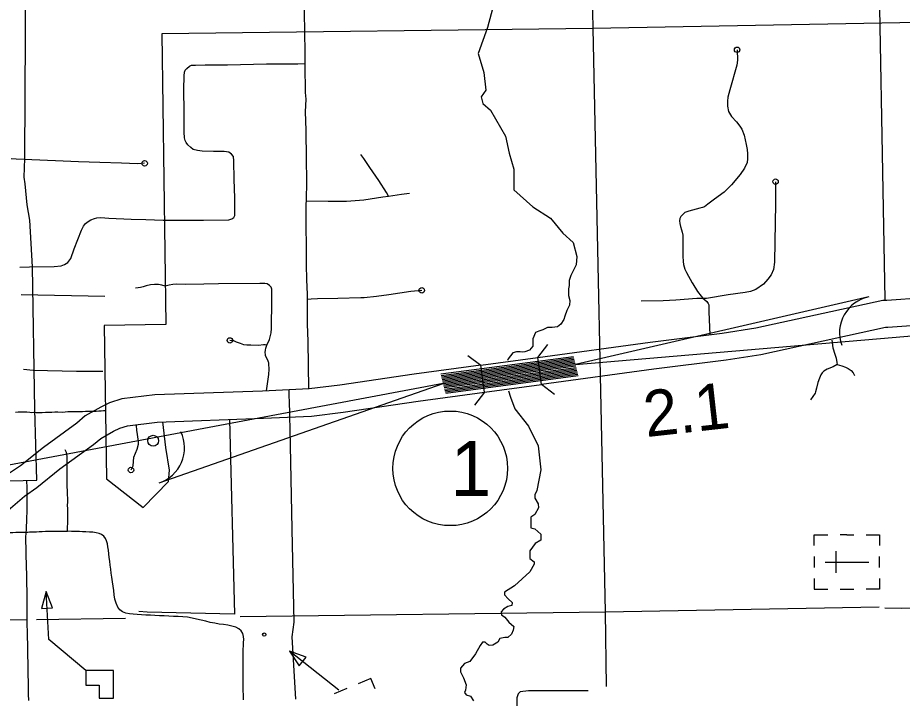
# Model space of a CAD drawing. Extents: x 1367863 to 1368197, y 380048 to 380261.
# Drawn here: x 1368012.13 to 1368043.62, y 380122.01 to 380146.25 of the extents above; entities that cross this region are included whole.
import ezdxf

# ---------------------------------------------------------------- set-up
doc = ezdxf.new("R2010")
doc.units = 0
for name, color, linetype in [('Level 10', 7, 'Continuous'), ('Level 31', 7, 'Continuous'), ('Level 32', 7, 'Continuous'), ('Level 33', 7, 'Continuous'), ('Level 35', 7, 'Continuous'), ('Level 37', 7, 'Continuous'), ('Level 48', 7, 'Continuous'), ('Level 5', 7, 'Continuous'), ('Level 57', 7, 'Continuous'), ('Level 58', 7, 'Continuous'), ('Level 6', 7, 'Continuous'), ('R_Border', 7, 'Continuous'), ('R_Dimension', 7, 'Continuous'), ('R_Draft', 7, 'Continuous')]:
    doc.layers.add(name, color=color, linetype=linetype)

msp = doc.modelspace()

# ---------------------------------------------------------------- linework, layer by layer
at = {"layer": 'Level 10'}
for points in [[(1368012.815, 380129.782), (1368012.748, 380132.296), (1368012.662, 380137.381), (1368012.568, 380139.037), (1368012.466, 380139.587), (1368012.395, 380140.33), (1368012.365, 380140.567), (1368012.387, 380141.231), (1368012.409, 380145.659), (1368012.399, 380151.1)], [(1368030.649, 380134.148), (1368034.65, 380134.691), (1368037.21, 380135.011), (1368038.401, 380135.199), (1368042.921, 380136.192), (1368043.069, 380136.191), (1368044.388, 380136.284)], [(1368044.428, 380135.314), (1368043.101, 380135.22), (1368043.024, 380135.221), (1368038.58, 380134.245), (1368037.346, 380134.05), (1368034.776, 380133.729), (1368030.779, 380133.187)], [(1368028.749, 380132.911), (1368028.618, 380133.873), (1368026.247, 380133.551), (1368023.595, 380133.158), (1368022.514, 380133.031), (1368020.845, 380132.951), (1368017.019, 380132.819), (1368015.838, 380132.673), (1368015.4, 380132.536), (1368015.088, 380132.377)], [(1368028.618, 380133.873), (1368030.649, 380134.148)], [(1368030.779, 380133.187), (1368030.649, 380134.148)], [(1368028.749, 380132.911), (1368030.779, 380133.187)], [(1368015.543, 380131.52), (1368015.767, 380131.634), (1368016.044, 380131.72), (1368017.096, 380131.85), (1368020.885, 380131.982), (1368022.594, 380132.064), (1368023.723, 380132.196), (1368026.384, 380132.591), (1368028.749, 380132.911)], [(1368015.088, 380132.377), (1368014.533, 380132.069), (1368014.234, 380131.812), (1368013.047, 380130.949), (1368012.237, 380130.295), (1368011.777, 380129.977)], [(1368011.633, 380128.564), (1368012.373, 380129.209), (1368012.818, 380129.517), (1368013.638, 380130.179), (1368014.837, 380131.051), (1368015.091, 380131.269), (1368015.543, 380131.52)], [(1368011.845, 380129.756), (1368012.815, 380129.782)]]:
    msp.add_lwpolyline(points, dxfattribs=at)
at = {"layer": 'Level 31'}
for points in [[(1368022.342, 380145.771), (1368022.342, 380145.735), (1368022.347, 380145.497), (1368022.352, 380145.261), (1368022.356, 380145.027), (1368022.36, 380144.794), (1368022.357, 380144.554), (1368022.371, 380143.587), (1368022.385, 380143.342), (1368022.375, 380143.122), (1368022.371, 380142.899), (1368022.388, 380142.239), (1368022.391, 380142.029), (1368022.393, 380141.824), (1368022.396, 380141.627), (1368022.4, 380141.437), (1368022.403, 380141.256), (1368022.404, 380141.082), (1368022.407, 380140.914), (1368022.409, 380140.752), (1368022.413, 380140.596), (1368022.415, 380140.446), (1368022.408, 380140.153), (1368022.404, 380140.015), (1368022.4, 380139.881), (1368022.397, 380139.743), (1368022.394, 380139.609), (1368022.393, 380139.473), (1368022.393, 380139.325), (1368022.391, 380139.176), (1368022.39, 380139.024), (1368022.39, 380138.866), (1368022.39, 380138.709), (1368022.394, 380138.547), (1368022.398, 380138.383), (1368022.4, 380138.211), (1368022.4, 380138.047), (1368022.404, 380137.886), (1368022.401, 380137.724), (1368022.406, 380137.571), (1368022.407, 380137.419), (1368022.405, 380137.261), (1368022.408, 380137.118), (1368022.412, 380136.976), (1368022.417, 380136.853), (1368022.421, 380136.721), (1368022.427, 380136.59), (1368022.432, 380136.459), (1368022.438, 380136.19), (1368022.435, 380136.043), (1368022.435, 380135.892), (1368022.434, 380135.737), (1368022.435, 380135.581), (1368022.438, 380135.423), (1368022.442, 380135.266), (1368022.447, 380135.11), (1368022.453, 380134.953), (1368022.456, 380134.806), (1368022.457, 380134.655), (1368022.46, 380134.499), (1368022.464, 380134.363), (1368022.469, 380134.23), (1368022.473, 380134.096), (1368022.476, 380133.976), (1368022.476, 380133.852), (1368022.474, 380133.733), (1368022.476, 380133.619), (1368022.477, 380133.509), (1368022.482, 380133.405), (1368022.487, 380133.305), (1368022.489, 380133.205), (1368022.488, 380133.03)], [(1368037.741, 380145.105), (1368037.75, 380144.733), (1368037.725, 380144.553), (1368037.48, 380143.681), (1368037.414, 380143.419), (1368037.398, 380143.272), (1368037.402, 380143.096), (1368037.435, 380142.908), (1368037.537, 380142.728), (1368037.713, 380142.544), (1368037.836, 380142.392), (1368037.905, 380142.282), (1368037.987, 380142.065), (1368038.065, 380141.731), (1368038.098, 380141.559), (1368038.11, 380141.395), (1368038.114, 380141.219), (1368038.093, 380141.092), (1368037.999, 380140.888), (1368037.844, 380140.667), (1368037.541, 380140.301), (1368037.275, 380140.039), (1368036.936, 380139.785), (1368036.694, 380139.605), (1368036.58, 380139.515), (1368036.51, 380139.49), (1368036.416, 380139.47), (1368036.023, 380139.36), (1368035.884, 380139.306), (1368035.831, 380139.269), (1368035.737, 380139.166), (1368035.704, 380139.1), (1368035.692, 380139.01), (1368035.696, 380138.924), (1368035.721, 380138.818), (1368035.762, 380138.699), (1368035.79, 380138.609), (1368035.803, 380138.507), (1368035.803, 380138.302), (1368035.807, 380137.754), (1368035.819, 380137.562), (1368035.827, 380137.455), (1368035.88, 380137.288), (1368035.942, 380137.177), (1368036.138, 380136.813), (1368036.161, 380136.766)], [(1368017.354, 380139.042), (1368018.006, 380139.036), (1368018.749, 380139.042), (1368019.652, 380139.049), (1368019.759, 380139.087), (1368019.822, 380139.137), (1368019.866, 380139.207), (1368019.866, 380139.301), (1368019.86, 380139.838), (1368019.841, 380140.489), (1368019.829, 380141.148), (1368019.81, 380141.306), (1368019.74, 380141.394), (1368019.645, 380141.464), (1368019.481, 380141.483), (1368019.109, 380141.483), (1368018.698, 380141.496), (1368018.528, 380141.514), (1368018.383, 380141.559), (1368018.301, 380141.628), (1368018.193, 380141.717), (1368018.13, 380141.799), (1368018.092, 380141.881), (1368018.067, 380141.976), (1368018.061, 380142.171), (1368018.054, 380142.891), (1368018.048, 380143.694), (1368018.054, 380144.176), (1368018.073, 380144.315), (1368018.099, 380144.378), (1368018.155, 380144.441), (1368018.244, 380144.517), (1368018.326, 380144.555), (1368018.465, 380144.561), (1368018.806, 380144.574), (1368019.601, 380144.574), (1368020.99, 380144.606), (1368021.764, 380144.606), (1368022.099, 380144.606), (1368022.358, 380144.612)], [(1368025.331, 380139.895), (1368025.261, 380140.026), (1368024.987, 380140.448), (1368024.672, 380140.91), (1368024.455, 380141.233), (1368024.353, 380141.376)], [(1368039.11, 380140.408), (1368039.106, 380139.626), (1368039.081, 380138.267), (1368039.065, 380137.547), (1368039.036, 380137.284), (1368038.95, 380137.087), (1368038.839, 380136.938), (1368038.685, 380136.755), (1368038.406, 380136.572), (1368038.214, 380136.495), (1368038.021, 380136.461), (1368037.42, 380136.379), (1368036.655, 380136.254), (1368036.304, 380136.244), (1368035.564, 380136.186), (1368035.111, 380136.171), (1368034.329, 380136.16)], [(1368022.397, 380139.727), (1368023.184, 380139.717), (1368023.842, 380139.717), (1368024.45, 380139.767), (1368025.127, 380139.867), (1368025.331, 380139.895), (1368025.797, 380139.969), (1368026.079, 380140.002)], [(1368021.007, 380134.589), (1368021.101, 380134.787), (1368021.153, 380135.024), (1368021.172, 380135.175), (1368021.172, 380135.315), (1368021.178, 380136.061), (1368021.175, 380136.576), (1368021.156, 380136.653), (1368021.101, 380136.713), (1368021.01, 380136.766), (1368020.933, 380136.782), (1368020.749, 380136.782), (1368019.282, 380136.768), (1368018.759, 380136.757), (1368018.121, 380136.752), (1368017.789, 380136.755), (1368017.657, 380136.744), (1368017.523, 380136.724), (1368017.378, 380136.683)], [(1368036.161, 380136.766), (1368036.335, 380136.499), (1368036.455, 380136.327), (1368036.518, 380136.264), (1368036.658, 380136.139), (1368036.71, 380136.077), (1368036.731, 380136.019), (1368036.736, 380135.769), (1368036.775, 380134.957)], [(1368026.518, 380136.538), (1368026.129, 380136.495), (1368025.338, 380136.38), (1368024.899, 380136.322), (1368024.46, 380136.272), (1368024.349, 380136.273), (1368023.524, 380136.253), (1368022.808, 380136.234), (1368022.578, 380136.225), (1368022.437, 380136.218)], [(1368021.007, 380134.589), (1368020.947, 380134.6), (1368020.886, 380134.597), (1368020.71, 380134.581), (1368020.435, 380134.586), (1368020.287, 380134.586), (1368020.182, 380134.603), (1368020.061, 380134.641), (1368019.926, 380134.691), (1368019.827, 380134.738), (1368019.687, 380134.757)], [(1368020.993, 380132.958), (1368021.07, 380133.546), (1368021.079, 380133.738), (1368021.07, 380133.923), (1368021.07, 380133.959), (1368021.062, 380133.984), (1368021.035, 380134.055), (1368020.969, 380134.182), (1368020.952, 380134.223), (1368020.949, 380134.253), (1368020.947, 380134.322), (1368020.955, 380134.413), (1368020.966, 380134.476), (1368021.007, 380134.589)], [(1368041.107, 380134.763), (1368041.149, 380134.496), (1368041.214, 380134.268), (1368041.263, 380134.123), (1368041.293, 380133.974), (1368041.298, 380133.904), (1368041.157, 380133.816), (1368040.951, 380133.737), (1368040.828, 380133.667), (1368040.767, 380133.606), (1368040.719, 380133.535), (1368040.671, 380133.413), (1368040.618, 380133.255), (1368040.565, 380133.062), (1368040.535, 380132.926), (1368040.513, 380132.873), (1368040.438, 380132.763), (1368040.355, 380132.645)], [(1368041.298, 380133.904), (1368041.464, 380133.856), (1368041.6, 380133.803), (1368041.697, 380133.755), (1368041.802, 380133.68), (1368041.868, 380133.597), (1368041.92, 380133.509)], [(1368016.347, 380131.73), (1368016.361, 380131.565), (1368016.422, 380131.17), (1368016.425, 380131.05), (1368016.372, 380130.871), (1368016.254, 380130.591), (1368016.243, 380130.451), (1368016.236, 380130.283), (1368016.165, 380130.141)], [(1368010.811, 380127.873), (1368010.881, 380127.878), (1368010.954, 380127.883), (1368011.029, 380127.887), (1368011.104, 380127.892), (1368011.181, 380127.897), (1368011.262, 380127.901), (1368011.348, 380127.905), (1368011.44, 380127.909), (1368011.536, 380127.911), (1368011.637, 380127.914), (1368011.743, 380127.918), (1368011.85, 380127.919), (1368011.958, 380127.922), (1368012.065, 380127.924), (1368012.163, 380127.927), (1368012.241, 380127.93), (1368012.29, 380127.93), (1368012.378, 380127.931), (1368012.429, 380127.932), (1368012.441, 380127.932)], [(1368012.477, 380124.632), (1368012.477, 380124.815), (1368012.467, 380125.024), (1368012.472, 380125.236), (1368012.471, 380125.444), (1368012.47, 380125.652), (1368012.467, 380125.859), (1368012.462, 380126.063), (1368012.457, 380126.264), (1368012.457, 380126.461), (1368012.452, 380126.66), (1368012.444, 380126.849), (1368012.437, 380127.025), (1368012.434, 380127.182), (1368012.434, 380127.313), (1368012.43, 380127.428), (1368012.425, 380127.531), (1368012.428, 380127.616), (1368012.429, 380127.692), (1368012.429, 380127.763), (1368012.437, 380127.883), (1368012.441, 380127.932)], [(1368012.441, 380127.932), (1368012.446, 380127.998), (1368012.451, 380128.09)], [(1368012.441, 380127.932), (1368012.491, 380127.933), (1368012.56, 380127.936), (1368012.636, 380127.939), (1368012.718, 380127.942), (1368012.807, 380127.945), (1368012.904, 380127.949), (1368013.008, 380127.954), (1368013.118, 380127.958), (1368013.232, 380127.96), (1368013.347, 380127.962), (1368013.46, 380127.964), (1368013.568, 380127.964), (1368013.666, 380127.962), (1368013.748, 380127.962), (1368013.911, 380127.966)], [(1368013.911, 380127.966), (1368013.912, 380128.094)], [(1368020.17, 380121.96), (1368020.167, 380122.123), (1368020.164, 380122.285), (1368020.161, 380122.445), (1368020.16, 380122.602), (1368020.16, 380122.757), (1368020.159, 380122.911), (1368020.159, 380123.063), (1368020.159, 380123.209), (1368020.154, 380123.36), (1368020.157, 380123.497), (1368020.16, 380123.63), (1368020.162, 380123.757), (1368020.166, 380123.878), (1368020.172, 380123.994), (1368020.179, 380124.106), (1368020.174, 380124.213), (1368020.146, 380124.317), (1368020.088, 380124.409), (1368020.004, 380124.486), (1368019.893, 380124.545), (1368019.759, 380124.584), (1368019.614, 380124.614), (1368019.464, 380124.635), (1368019.308, 380124.656), (1368019.149, 380124.685), (1368018.986, 380124.714), (1368018.825, 380124.755), (1368018.665, 380124.797), (1368018.504, 380124.835), (1368018.343, 380124.871), (1368018.181, 380124.896), (1368018.014, 380124.912), (1368017.848, 380124.92), (1368017.679, 380124.929), (1368017.511, 380124.938), (1368017.343, 380124.946), (1368017.18, 380124.952), (1368017.018, 380124.96), (1368016.857, 380124.97), (1368016.698, 380124.978), (1368016.541, 380124.986), (1368016.388, 380124.995), (1368016.241, 380125.007), (1368016.108, 380125.017), (1368015.982, 380125.044), (1368015.87, 380125.096), (1368015.773, 380125.168), (1368015.695, 380125.263), (1368015.637, 380125.395), (1368015.597, 380125.544), (1368015.572, 380125.699), (1368015.555, 380125.845), (1368015.532, 380126.007), (1368015.511, 380126.165), (1368015.486, 380126.32), (1368015.462, 380126.467), (1368015.445, 380126.614), (1368015.428, 380126.756), (1368015.413, 380126.895), (1368015.395, 380127.028), (1368015.379, 380127.161), (1368015.364, 380127.283), (1368015.348, 380127.4), (1368015.327, 380127.51), (1368015.298, 380127.616), (1368015.258, 380127.708), (1368015.199, 380127.783), (1368015.122, 380127.841), (1368015.031, 380127.881), (1368014.927, 380127.907), (1368014.811, 380127.923), (1368014.686, 380127.933), (1368014.565, 380127.94), (1368014.445, 380127.945), (1368014.333, 380127.95), (1368014.228, 380127.949), (1368014.134, 380127.953), (1368014.05, 380127.956), (1368013.911, 380127.966)], [(1368047.184, 380125.273), (1368046.31, 380125.259), (1368045.594, 380125.259), (1368045.157, 380125.266), (1368044.488, 380125.233), (1368043.594, 380125.213), (1368042.998, 380125.22)], [(1368012.525, 380121.929), (1368012.521, 380122.162), (1368012.517, 380122.389), (1368012.513, 380122.614), (1368012.51, 380122.837), (1368012.506, 380123.059), (1368012.504, 380123.282), (1368012.499, 380123.507), (1368012.493, 380123.731), (1368012.489, 380123.956), (1368012.488, 380124.177), (1368012.479, 380124.393), (1368012.477, 380124.632)]]:
    msp.add_lwpolyline(points, dxfattribs=at)
for centre in [(1368037.741, 380145.105), (1368039.11, 380140.408), (1368026.518, 380136.538), (1368019.687, 380134.757), (1368016.165, 380130.141)]:
    msp.add_circle(centre, 0.097, dxfattribs=at)
at = {"layer": 'Level 32'}
for points in [[(1368043.011, 380136.212), (1368042.731, 380151.129), (1368042.659, 380154.556), (1368042.643, 380154.618), (1368042.607, 380154.662), (1368042.594, 380154.674), (1368042.578, 380154.694), (1368042.51, 380154.734), (1368041.154, 380154.752)], [(1368032.436, 380122.274), (1368030.311, 380122.274), (1368030.018, 380122.244), (1368029.951, 380122.177), (1368029.898, 380122.027), (1368029.906, 380121.381), (1368029.921, 380120.419), (1368029.951, 380119.69), (1368029.958, 380119.375)]]:
    msp.add_lwpolyline(points, dxfattribs=at)
at = {"layer": 'Level 33'}
for points in [[(1368022.251, 380150.262), (1368022.259, 380150.054), (1368022.268, 380149.846), (1368022.274, 380149.639), (1368022.278, 380149.432), (1368022.283, 380149.211), (1368022.283, 380149.004), (1368022.286, 380148.799), (1368022.287, 380148.593), (1368022.288, 380148.388), (1368022.291, 380148.184), (1368022.296, 380147.976), (1368022.302, 380147.766), (1368022.306, 380147.556), (1368022.31, 380147.334), (1368022.313, 380147.114), (1368022.316, 380146.892), (1368022.324, 380146.667), (1368022.328, 380146.439), (1368022.334, 380146.207), (1368022.339, 380145.972), (1368022.342, 380145.771)], [(1368016.652, 380141.063), (1368016.403, 380141.048), (1368015.83, 380141.068), (1368015.058, 380141.093), (1368014.301, 380141.113), (1368013.479, 380141.148), (1368012.642, 380141.188), (1368012.084, 380141.207), (1368011.907, 380141.218)], [(1368012.211, 380137.362), (1368012.558, 380137.381), (1368013.436, 380137.394), (1368013.682, 380137.407), (1368013.795, 380137.457), (1368013.915, 380137.527), (1368014.023, 380137.678), (1368014.149, 380138.013), (1368014.402, 380138.682), (1368014.477, 380138.828), (1368014.547, 380138.916), (1368014.641, 380138.992), (1368014.742, 380139.055), (1368014.862, 380139.099), (1368014.951, 380139.125), (1368015.09, 380139.137), (1368015.374, 380139.112), (1368016.169, 380139.074), (1368016.693, 380139.061), (1368017.312, 380139.042), (1368017.354, 380139.042)], [(1368017.378, 380136.683), (1368017.268, 380136.724), (1368017.141, 380136.746), (1368017.006, 380136.752), (1368016.855, 380136.741), (1368016.707, 380136.705), (1368016.605, 380136.664), (1368016.5, 380136.639), (1368016.423, 380136.625), (1368016.33, 380136.617)], [(1368012.258, 380136.395), (1368015.234, 380136.33)], [(1368015.161, 380133.647), (1368014.223, 380133.647), (1368012.686, 380133.688), (1368012.341, 380133.715)], [(1368012.379, 380132.198), (1368012.317, 380132.196), (1368012.239, 380132.196), (1368012.151, 380132.196), (1368012.051, 380132.192)], [(1368015.257, 380132.249), (1368015.193, 380132.247), (1368015.108, 380132.241), (1368015.021, 380132.236), (1368014.932, 380132.23), (1368014.841, 380132.23), (1368014.746, 380132.23), (1368014.646, 380132.225), (1368014.545, 380132.224), (1368014.445, 380132.219), (1368014.339, 380132.216), (1368014.235, 380132.213), (1368014.127, 380132.213), (1368013.917, 380132.209), (1368013.818, 380132.201), (1368013.723, 380132.191), (1368013.568, 380132.203), (1368013.457, 380132.2), (1368013.354, 380132.194), (1368013.233, 380132.192), (1368013.121, 380132.187), (1368013.007, 380132.183), (1368012.896, 380132.181), (1368012.794, 380132.182), (1368012.703, 380132.184), (1368012.623, 380132.183), (1368012.561, 380132.188), (1368012.465, 380132.196), (1368012.379, 380132.198)], [(1368013.912, 380128.094), (1368013.912, 380128.138), (1368013.917, 380128.209), (1368013.918, 380128.281), (1368013.92, 380128.364), (1368013.92, 380128.453), (1368013.918, 380128.551), (1368013.916, 380128.656), (1368013.914, 380128.766), (1368013.912, 380128.883), (1368013.915, 380129.008), (1368013.915, 380129.136), (1368013.909, 380129.263), (1368013.905, 380129.407), (1368013.899, 380129.542), (1368013.897, 380129.685), (1368013.895, 380129.831), (1368013.893, 380129.978), (1368013.891, 380130.121), (1368013.891, 380130.264), (1368013.891, 380130.397), (1368013.892, 380130.519), (1368013.894, 380130.625), (1368013.888, 380130.707), (1368013.875, 380130.76), (1368013.826, 380130.864)], [(1368012.451, 380128.09), (1368012.453, 380128.166), (1368012.456, 380128.267), (1368012.46, 380128.375), (1368012.464, 380128.489), (1368012.469, 380128.605), (1368012.473, 380128.723), (1368012.475, 380128.842), (1368012.475, 380128.959), (1368012.476, 380129.07), (1368012.474, 380129.174), (1368012.472, 380129.271), (1368012.47, 380129.361), (1368012.469, 380129.443), (1368012.468, 380129.516), (1368012.461, 380129.762)]]:
    msp.add_lwpolyline(points, dxfattribs=at)
msp.add_circle((1368016.652, 380141.063), 0.097, dxfattribs=at)
at = {"layer": 'Level 35'}
for points in [[(1368029.116, 380146.89), (1368028.859, 380145.904), (1368028.525, 380144.968), (1368028.726, 380144.299), (1368028.792, 380143.663), (1368028.625, 380143.429), (1368028.692, 380143.195), (1368028.96, 380142.961), (1368029.495, 380142.025), (1368029.629, 380141.423), (1368029.796, 380140.854), (1368029.796, 380140.486), (1368029.796, 380140.119), (1368030.465, 380139.517), (1368031.1, 380139.115), (1368031.535, 380138.58), (1368031.903, 380138.246), (1368032.037, 380137.744), (1368032.012, 380137.45), (1368031.818, 380137.07), (1368031.762, 380136.894), (1368031.762, 380136.718), (1368031.744, 380136.598), (1368031.744, 380136.468), (1368031.744, 380136.357)], [(1368031.744, 380136.357), (1368031.79, 380136.181), (1368031.771, 380136.014), (1368031.679, 380135.82), (1368031.605, 380135.616), (1368031.568, 380135.505), (1368031.466, 380135.338), (1368031.346, 380135.237), (1368031.161, 380135.218), (1368030.994, 380135.218), (1368030.827, 380135.135), (1368030.679, 380135.088), (1368030.559, 380135.033), (1368030.475, 380134.811), (1368030.475, 380134.699), (1368030.475, 380134.551), (1368030.355, 380134.412), (1368030.189, 380134.348), (1368030.114, 380134.338), (1368030.013, 380134.348), (1368029.883, 380134.348), (1368029.763, 380134.31), (1368029.596, 380134.097), (1368029.572, 380134.043)], [(1368029.606, 380132.963), (1368029.679, 380132.741), (1368029.828, 380132.325), (1368030.317, 380131.698), (1368030.655, 380131.002), (1368030.754, 380130.148), (1368030.615, 380129.412), (1368030.536, 380129.253), (1368030.536, 380129.134), (1368030.655, 380128.936), (1368030.675, 380128.796), (1368030.536, 380128.558), (1368030.397, 380128.459), (1368030.397, 380128.081), (1368030.536, 380128.041), (1368030.754, 380127.862), (1368030.754, 380127.644), (1368030.556, 380127.524), (1368030.357, 380127.266), (1368030.357, 380126.988), (1368030.516, 380126.869), (1368030.516, 380126.789), (1368030.357, 380126.511), (1368029.82, 380126.014), (1368029.466, 380125.794), (1368029.466, 380125.702), (1368029.587, 380125.553), (1368029.735, 380125.424), (1368029.726, 380125.313), (1368029.578, 380125.276), (1368029.42, 380125.192), (1368029.346, 380125.09), (1368029.355, 380124.989), (1368029.476, 380124.896), (1368029.615, 380124.72), (1368029.79, 380124.563), (1368029.772, 380124.442), (1368029.707, 380124.294), (1368029.578, 380124.183), (1368029.476, 380124.183), (1368029.3, 380124.137), (1368029.226, 380124.016), (1368029.041, 380123.905), (1368028.911, 380123.896), (1368028.846, 380123.942), (1368028.772, 380124.016), (1368028.68, 380124.016), (1368028.596, 380123.896), (1368028.43, 380123.59), (1368028.226, 380123.322), (1368028.032, 380123.248), (1368027.893, 380123.09), (1368027.893, 380122.951), (1368028.004, 380122.738), (1368028.096, 380122.497), (1368028.069, 380122.307), (1368028.041, 380122.214), (1368028.096, 380122.14), (1368028.254, 380122.085), (1368028.356, 380121.927)]]:
    msp.add_lwpolyline(points, dxfattribs=at)
at = {"layer": 'Level 37'}
for points in [[(1368030.649, 380134.148), (1368031.002, 380134.611)], [(1368028.155, 380134.225), (1368028.618, 380133.873)], [(1368031.243, 380132.834), (1368030.779, 380133.187)], [(1368028.749, 380132.911), (1368028.396, 380132.448)]]:
    msp.add_lwpolyline(points, dxfattribs=at)
at = {"layer": 'Level 5'}
for points in [[(1368052.541, 380146.238), (1368032.607, 380145.868)], [(1368032.607, 380145.868), (1368033.044, 380125.092)], [(1368020.052, 380124.92), (1368033.044, 380125.092)], [(1368033.044, 380125.092), (1368042.795, 380125.271)], [(1368033.044, 380125.092), (1368033.083, 380122.436)], [(1368008.395, 380124.769), (1368012.457, 380124.82)], [(1368012.803, 380124.82), (1368015.976, 380124.862)]]:
    msp.add_lwpolyline(points, dxfattribs=at)
at = {"layer": 'Level 57'}
for p, q in [((1368041.649, 380127.836), (1368041.41, 380127.836)), ((1368041.649, 380127.836), (1368041.895, 380127.836)), ((1368040.485, 380127.062), (1368040.485, 380126.674)), ((1368041.261, 380126.477), (1368041.261, 380127.257)), ((1368042.813, 380126.674), (1368042.813, 380127.062)), ((1368040.873, 380126.865), (1368042.425, 380126.865)), ((1368041.649, 380126.865), (1368041.649, 380126.865)), ((1368041.649, 380126.865), (1368041.649, 380126.865)), ((1368041.41, 380125.895), (1368041.895, 380125.895)), ((1368023.849, 380122.361), (1368023.4, 380122.176))]:
    msp.add_line(p, q, dxfattribs=at)
for points in [[(1368040.485, 380127.448), (1368040.485, 380127.836), (1368040.97, 380127.836)], [(1368042.328, 380127.836), (1368042.813, 380127.836), (1368042.813, 380127.448)], [(1368040.485, 380126.283), (1368040.485, 380125.895), (1368040.97, 380125.895)], [(1368042.813, 380126.283), (1368042.813, 380125.895), (1368042.328, 380125.895)], [(1368023.562, 380122.303), (1368021.809, 380123.696)], [(1368024.852, 380122.355), (1368024.704, 380122.714), (1368024.256, 380122.529)]]:
    msp.add_lwpolyline(points, dxfattribs=at)
msp.add_lwpolyline([(1368022.151, 380123.172), (1368022.397, 380123.482), (1368021.809, 380123.696)], close=True, dxfattribs=at)
msp.add_circle((1368020.91, 380124.281), 0.0582, dxfattribs=at)
at = {"layer": 'Level 58'}
for points in [[(1368012.982, 380125.214), (1368013.377, 380125.236), (1368013.146, 380125.818)], [(1368015.548, 380122.997), (1368014.562, 380122.997), (1368014.562, 380122.477), (1368015.029, 380122.477), (1368015.029, 380122.011), (1368015.548, 380122.011)]]:
    msp.add_lwpolyline(points, close=True, dxfattribs=at)
msp.add_lwpolyline([(1368014.562, 380122.997), (1368013.242, 380124.102), (1368013.146, 380125.818)], dxfattribs=at)
msp.add_circle((1368016.956, 380131.183), 0.194, dxfattribs=at)
at = {"layer": 'Level 6'}
for points in [[(1368032.386, 380156.557), (1368032.607, 380145.868)], [(1368032.607, 380145.868), (1368017.259, 380145.675)], [(1368017.259, 380145.675), (1368017.408, 380135.32), (1368015.213, 380135.286)], [(1368015.213, 380135.286), (1368015.292, 380129.824)], [(1368015.292, 380129.824), (1368016.595, 380128.811), (1368017.499, 380129.727), (1368017.533, 380130.134), (1368017.409, 380130.948), (1368017.294, 380131.857)], [(1368019.668, 380131.94), (1368019.852, 380125.011)], [(1368019.849, 380125.011), (1368016.742, 380125.082), (1368016.449, 380125.099)]]:
    msp.add_lwpolyline(points, dxfattribs=at)
at = {"layer": 'R_Border'}
msp.add_lwpolyline([(1368022.031, 380121.983), (1368021.909, 380124.203), (1368021.973, 380124.721), (1368021.905, 380128.04), (1368021.845, 380131.019), (1368021.807, 380132.633), (1368021.796, 380132.728), (1368021.794, 380132.888), (1368021.799, 380133.01)], dxfattribs=at)
msp.add_circle((1368027.528, 380130.201), 2.041, dxfattribs=at)
at = {"layer": 'R_Dimension'}
for p, q in [((1368027.194, 380133.562), (1368031.915, 380134.188)), ((1368027.206, 380133.513), (1368031.928, 380134.139)), ((1368027.218, 380133.464), (1368031.94, 380134.09)), ((1368027.231, 380133.415), (1368031.952, 380134.041)), ((1368027.243, 380133.367), (1368031.965, 380133.992)), ((1368027.255, 380133.318), (1368031.977, 380133.944)), ((1368027.268, 380133.269), (1368031.989, 380133.895)), ((1368027.28, 380133.22), (1368032.002, 380133.846)), ((1368027.292, 380133.171), (1368032.014, 380133.797)), ((1368027.305, 380133.123), (1368032.027, 380133.748)), ((1368027.317, 380133.074), (1368032.039, 380133.7)), ((1368027.33, 380133.025), (1368032.051, 380133.651)), ((1368027.342, 380132.976), (1368032.064, 380133.602)), ((1368027.354, 380132.927), (1368032.076, 380133.553)), ((1368027.367, 380132.879), (1368032.088, 380133.504))]:
    msp.add_line(p, q, dxfattribs=at)
at = {"layer": 'R_Draft'}
for p, q in [((1368042.43, 380136.308), (1368031.989, 380133.895)), ((1368017.166, 380129.684), (1368027.28, 380133.22))]:
    msp.add_line(p, q, dxfattribs=at)
for points in [[(1368031.989, 380133.895), (1368065.24, 380136.731)], [(1368027.28, 380133.22), (1367942.971, 380117.362)]]:
    msp.add_lwpolyline(points, dxfattribs=at)
for centre, start, end in [((1368042.684, 380135.033), 101.285, 199.9554), ((1368016.774, 380130.923), 287.5393, 26.2096)]:
    msp.add_arc(centre, 1.299, start, end, dxfattribs=at)

# ---------------------------------------------------------------- texts
at = {"layer": 'Level 48'}
msp.add_text('2.1', height=1.6394, rotation=6.4008, dxfattribs=at).set_placement((1368034.505, 380131.31))
at = {"layer": 'R_Border'}
msp.add_text('1', height=1.959, dxfattribs=at).set_placement((1368027.537, 380129.221))

doc.saveas('drawing.dxf')
